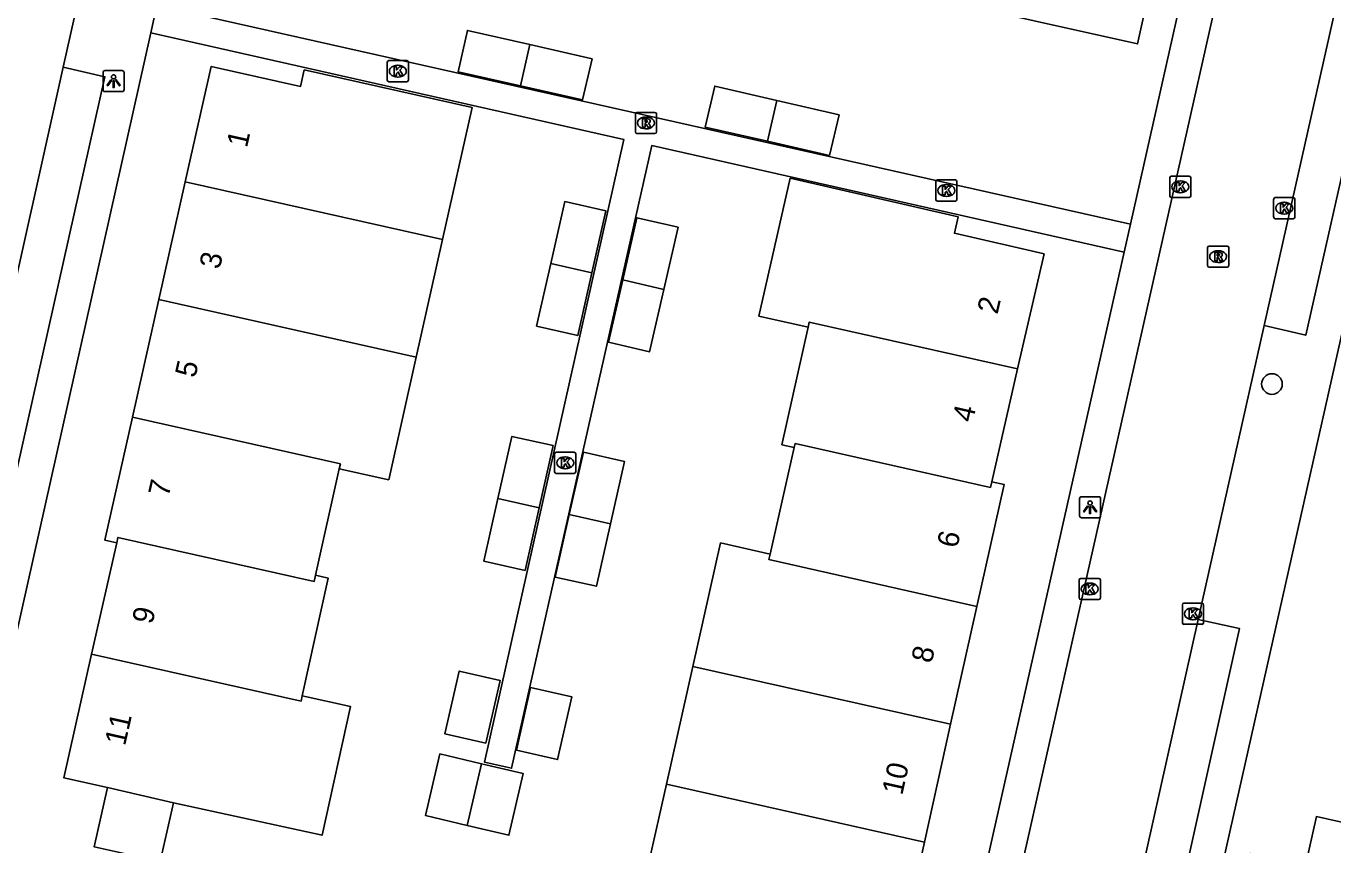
# Model space of a CAD drawing. Extents: x 161771 to 163125, y 382479 to 383177.
# Drawn here: x 162643.4 to 162705.3, y 382625.6 to 382664.4 of the extents above; entities that cross this region are included whole.
import ezdxf

# ---------------------------------------------------------------- set-up
doc = ezdxf.new("R2010")
doc.units = 0
for name, color, linetype in [('IMGEO_Boom', 7, 'Continuous'), ('IMGEO_Kolk', 7, 'Continuous'), ('IMGEO_Lichtpunt', 7, 'Continuous'), ('IMGEO_Pand', 7, 'Continuous'), ('IMGEO_Pand_nummerreeks', 7, 'Continuous'), ('IMGEO_Rijbaan_lokaal_open', 7, 'Continuous'), ('IMGEO_Rioolput', 7, 'Continuous'), ('IMGEO_Voetpad_open', 7, 'Continuous')]:
    doc.layers.add(name, color=color, linetype=linetype)

msp = doc.modelspace()

# ---------------------------------------------------------------- linework, layer by layer
at = {"layer": 'IMGEO_Boom'}
msp.add_circle((162702.369, 382647.447), 0.489, dxfattribs=at)
at = {"layer": 'IMGEO_Kolk'}
for p, q in [((162660.568, 382662.751), (162661.42, 382662.751)), ((162660.493, 382661.825), (162660.493, 382662.677)), ((162660.981, 382662.531), (162661.006, 382662.531)), ((162661.494, 382662.677), (162661.494, 382661.825)), ((162661.42, 382661.751), (162660.568, 382661.751)), ((162661.004, 382661.971), (162660.979, 382661.971)), ((162697.529, 382656.353), (162697.529, 382657.205)), ((162697.604, 382657.279), (162698.456, 382657.279)), ((162698.53, 382657.205), (162698.53, 382656.353)), ((162686.456, 382656.181), (162686.456, 382657.033)), ((162686.531, 382657.107), (162687.383, 382657.107)), ((162686.944, 382656.887), (162686.969, 382656.887)), ((162687.457, 382657.033), (162687.457, 382656.181)), ((162698.017, 382657.059), (162698.042, 382657.059)), ((162687.383, 382656.107), (162686.531, 382656.107)), ((162686.967, 382656.327), (162686.942, 382656.327)), ((162698.456, 382656.279), (162697.604, 382656.279)), ((162698.04, 382656.499), (162698.015, 382656.499)), ((162702.449, 382655.341), (162702.449, 382656.193)), ((162702.524, 382656.267), (162703.376, 382656.267)), ((162702.937, 382656.047), (162702.962, 382656.047)), ((162703.45, 382656.193), (162703.45, 382655.341)), ((162702.96, 382655.487), (162702.935, 382655.487)), ((162703.376, 382655.267), (162702.524, 382655.267)), ((162668.49, 382644.219), (162669.342, 382644.219)), ((162668.415, 382643.293), (162668.415, 382644.145)), ((162668.903, 382643.999), (162668.928, 382643.999)), ((162669.416, 382644.145), (162669.416, 382643.293)), ((162669.342, 382643.219), (162668.49, 382643.219)), ((162668.926, 382643.439), (162668.901, 382643.439)), ((162693.244, 382637.324), (162693.244, 382638.176)), ((162693.319, 382638.25), (162694.171, 382638.25)), ((162693.732, 382638.03), (162693.757, 382638.03)), ((162694.245, 382638.176), (162694.245, 382637.324)), ((162693.755, 382637.47), (162693.73, 382637.47)), ((162694.171, 382637.25), (162693.319, 382637.25)), ((162698.129, 382636.149), (162698.129, 382637.001)), ((162698.204, 382637.075), (162699.056, 382637.075)), ((162698.617, 382636.855), (162698.642, 382636.855)), ((162699.13, 382637.001), (162699.13, 382636.149)), ((162698.64, 382636.295), (162698.615, 382636.295)), ((162699.056, 382636.075), (162698.204, 382636.075))]:
    msp.add_line(p, q, dxfattribs=at)
for points in [[(162660.568, 382662.751), (162661.42, 382662.751)], [(162660.493, 382661.825), (162660.493, 382662.677)], [(162660.814, 382662.451), (162660.937, 382662.451), (162660.937, 382662.3), (162661.067, 382662.451), (162661.231, 382662.451), (162661.085, 382662.3), (162661.238, 382662.051), (162661.086, 382662.051), (162661.001, 382662.215), (162660.937, 382662.148), (162660.937, 382662.051), (162660.814, 382662.051), (162660.814, 382662.451)], [(162661.494, 382662.677), (162661.494, 382661.825)], [(162661.42, 382661.751), (162660.568, 382661.751)], [(162697.529, 382656.353), (162697.529, 382657.205)], [(162697.604, 382657.279), (162698.456, 382657.279)], [(162698.53, 382657.205), (162698.53, 382656.353)], [(162686.456, 382656.181), (162686.456, 382657.033)], [(162686.531, 382657.107), (162687.383, 382657.107)], [(162686.777, 382656.807), (162686.9, 382656.807), (162686.9, 382656.656), (162687.03, 382656.807), (162687.194, 382656.807), (162687.048, 382656.656), (162687.201, 382656.407), (162687.049, 382656.407), (162686.964, 382656.571), (162686.9, 382656.504), (162686.9, 382656.407), (162686.777, 382656.407), (162686.777, 382656.807)], [(162687.457, 382657.033), (162687.457, 382656.181)], [(162697.85, 382656.979), (162697.973, 382656.979), (162697.973, 382656.828), (162698.103, 382656.979), (162698.267, 382656.979), (162698.121, 382656.828), (162698.274, 382656.579), (162698.122, 382656.579), (162698.037, 382656.743), (162697.973, 382656.676), (162697.973, 382656.579), (162697.85, 382656.579), (162697.85, 382656.979)], [(162687.383, 382656.107), (162686.531, 382656.107)], [(162698.456, 382656.279), (162697.604, 382656.279)], [(162702.449, 382655.341), (162702.449, 382656.193)], [(162702.524, 382656.267), (162703.376, 382656.267)], [(162702.77, 382655.967), (162702.893, 382655.967), (162702.893, 382655.816), (162703.023, 382655.967), (162703.187, 382655.967), (162703.041, 382655.816), (162703.194, 382655.567), (162703.042, 382655.567), (162702.957, 382655.731), (162702.893, 382655.664), (162702.893, 382655.567), (162702.77, 382655.567), (162702.77, 382655.967)], [(162703.45, 382656.193), (162703.45, 382655.341)], [(162703.376, 382655.267), (162702.524, 382655.267)], [(162668.49, 382644.219), (162669.342, 382644.219)], [(162668.415, 382643.293), (162668.415, 382644.145)], [(162668.736, 382643.919), (162668.859, 382643.919), (162668.859, 382643.768), (162668.989, 382643.919), (162669.153, 382643.919), (162669.007, 382643.768), (162669.16, 382643.519), (162669.008, 382643.519), (162668.923, 382643.683), (162668.859, 382643.616), (162668.859, 382643.519), (162668.736, 382643.519), (162668.736, 382643.919)], [(162669.416, 382644.145), (162669.416, 382643.293)], [(162669.342, 382643.219), (162668.49, 382643.219)], [(162693.244, 382637.324), (162693.244, 382638.176)], [(162693.319, 382638.25), (162694.171, 382638.25)], [(162694.245, 382638.176), (162694.245, 382637.324)], [(162693.565, 382637.95), (162693.688, 382637.95), (162693.688, 382637.799), (162693.818, 382637.95), (162693.982, 382637.95), (162693.836, 382637.799), (162693.989, 382637.55), (162693.837, 382637.55), (162693.752, 382637.714), (162693.688, 382637.647), (162693.688, 382637.55), (162693.565, 382637.55), (162693.565, 382637.95)], [(162694.171, 382637.25), (162693.319, 382637.25)], [(162698.129, 382636.149), (162698.129, 382637.001)], [(162698.204, 382637.075), (162699.056, 382637.075)], [(162698.45, 382636.775), (162698.573, 382636.775), (162698.573, 382636.624), (162698.703, 382636.775), (162698.867, 382636.775), (162698.721, 382636.624), (162698.874, 382636.375), (162698.722, 382636.375), (162698.637, 382636.539), (162698.573, 382636.472), (162698.573, 382636.375), (162698.45, 382636.375), (162698.45, 382636.775)], [(162699.13, 382637.001), (162699.13, 382636.149)], [(162699.056, 382636.075), (162698.204, 382636.075)]]:
    msp.add_lwpolyline(points, dxfattribs=at)
for centre, start, end in [((162660.57, 382662.675), 91.55205, 178.44795), ((162660.57, 382662.675), 91.55205, 178.44795), ((162661.418, 382662.675), 1.55205, 88.44795), ((162661.418, 382662.675), 1.55205, 88.44795), ((162660.57, 382661.827), 181.55205, 268.44795), ((162660.57, 382661.827), 181.55205, 268.44795), ((162661.418, 382661.827), 271.55205, 358.44795), ((162661.418, 382661.827), 271.55205, 358.44795), ((162697.606, 382657.203), 91.55205, 178.44795), ((162697.606, 382657.203), 91.55205, 178.44795), ((162698.454, 382657.203), 1.55205, 88.44795), ((162698.454, 382657.203), 1.55205, 88.44795), ((162686.533, 382657.031), 91.55205, 178.44795), ((162686.533, 382657.031), 91.55205, 178.44795), ((162687.381, 382657.031), 1.55205, 88.44795), ((162687.381, 382657.031), 1.55205, 88.44795), ((162686.533, 382656.183), 181.55205, 268.44795), ((162686.533, 382656.183), 181.55205, 268.44795), ((162687.381, 382656.183), 271.55205, 358.44795), ((162687.381, 382656.183), 271.55205, 358.44795), ((162697.606, 382656.355), 181.55205, 268.44795), ((162697.606, 382656.355), 181.55205, 268.44795), ((162698.454, 382656.355), 271.55205, 358.44795), ((162698.454, 382656.355), 271.55205, 358.44795), ((162702.526, 382656.191), 91.55205, 178.44795), ((162702.526, 382656.191), 91.55205, 178.44795), ((162703.374, 382656.191), 1.55205, 88.44795), ((162703.374, 382656.191), 1.55205, 88.44795), ((162702.526, 382655.343), 181.55205, 268.44795), ((162702.526, 382655.343), 181.55205, 268.44795), ((162703.374, 382655.343), 271.55205, 358.44795), ((162703.374, 382655.343), 271.55205, 358.44795), ((162668.492, 382644.143), 91.55205, 178.44795), ((162668.492, 382644.143), 91.55205, 178.44795), ((162669.34, 382644.143), 1.55205, 88.44795), ((162669.34, 382644.143), 1.55205, 88.44795), ((162668.492, 382643.295), 181.55205, 268.44795), ((162668.492, 382643.295), 181.55205, 268.44795), ((162669.34, 382643.295), 271.55205, 358.44795), ((162669.34, 382643.295), 271.55205, 358.44795), ((162693.321, 382638.174), 91.55205, 178.44795), ((162693.321, 382638.174), 91.55205, 178.44795), ((162694.169, 382638.174), 1.55205, 88.44795), ((162694.169, 382638.174), 1.55205, 88.44795), ((162693.321, 382637.326), 181.55205, 268.44795), ((162693.321, 382637.326), 181.55205, 268.44795), ((162694.169, 382637.326), 271.55205, 358.44795), ((162694.169, 382637.326), 271.55205, 358.44795), ((162698.206, 382636.999), 91.55205, 178.44795), ((162698.206, 382636.999), 91.55205, 178.44795), ((162699.054, 382636.999), 1.55205, 88.44795), ((162699.054, 382636.999), 1.55205, 88.44795), ((162698.206, 382636.151), 181.55205, 268.44795), ((162698.206, 382636.151), 181.55205, 268.44795), ((162699.054, 382636.151), 271.55205, 358.44795), ((162699.054, 382636.151), 271.55205, 358.44795)]:
    msp.add_arc(centre, 0.0765, start, end, dxfattribs=at)
for centre, major_axis, ratio, start_param, end_param in [((162660.98, 382662.251), (-0.387, 0.002), 0.722429, 4.712389, 7.853982), ((162661.005, 382662.251), (-0.39, 0.002), 0.717154, 1.570796, 4.712389), ((162686.943, 382656.607), (-0.387, 0.002), 0.722429, 4.712389, 7.853982), ((162686.968, 382656.607), (-0.39, 0.002), 0.717154, 1.570796, 4.712389), ((162698.016, 382656.779), (-0.387, 0.002), 0.722429, 4.712389, 7.853982), ((162698.041, 382656.779), (-0.39, 0.002), 0.717154, 1.570796, 4.712389), ((162702.936, 382655.767), (-0.387, 0.002), 0.722429, 4.712389, 7.853982), ((162702.961, 382655.767), (-0.39, 0.002), 0.717154, 1.570796, 4.712389), ((162668.902, 382643.719), (-0.387, 0.002), 0.722429, 4.712389, 7.853982), ((162668.927, 382643.719), (-0.39, 0.002), 0.717154, 1.570796, 4.712389), ((162693.731, 382637.75), (-0.387, 0.002), 0.722429, 4.712389, 7.853982), ((162693.756, 382637.75), (-0.39, 0.002), 0.717154, 1.570796, 4.712389), ((162698.616, 382636.575), (-0.387, 0.002), 0.722429, 4.712389, 7.853982), ((162698.641, 382636.575), (-0.39, 0.002), 0.717154, 1.570796, 4.712389)]:
    msp.add_ellipse(centre, major_axis=major_axis, ratio=ratio, start_param=start_param, end_param=end_param, dxfattribs=at)
at = {"layer": 'IMGEO_Lichtpunt'}
for p, q in [((162647.04, 382662.184), (162647.04, 382661.377)), ((162647.04, 382662.184), (162647.04, 382661.377)), ((162647.942, 382662.279), (162647.134, 382662.279)), ((162647.942, 382662.279), (162647.134, 382662.279)), ((162648.036, 382661.377), (162648.036, 382662.184)), ((162648.036, 382661.377), (162648.036, 382662.184)), ((162647.134, 382661.283), (162647.942, 382661.283)), ((162647.134, 382661.283), (162647.942, 382661.283)), ((162693.261, 382642.02), (162693.261, 382641.213)), ((162693.261, 382642.02), (162693.261, 382641.213)), ((162694.163, 382642.115), (162693.355, 382642.115)), ((162694.163, 382642.115), (162693.355, 382642.115)), ((162694.257, 382641.213), (162694.257, 382642.02)), ((162694.257, 382641.213), (162694.257, 382642.02)), ((162693.355, 382641.119), (162694.163, 382641.119)), ((162693.355, 382641.119), (162694.163, 382641.119))]:
    msp.add_line(p, q, dxfattribs=at)
for points in [[(162647.414, 382661.848), (162647.453, 382661.82), (162647.265, 382661.558), (162647.227, 382661.585), (162647.414, 382661.848)], [(162647.516, 382661.8), (162647.563, 382661.8), (162647.563, 382661.478), (162647.516, 382661.478), (162647.516, 382661.8)], [(162647.626, 382661.82), (162647.664, 382661.847), (162647.851, 382661.585), (162647.812, 382661.557), (162647.626, 382661.82)], [(162693.635, 382641.684), (162693.674, 382641.656), (162693.486, 382641.394), (162693.448, 382641.421), (162693.635, 382641.684)], [(162693.737, 382641.636), (162693.784, 382641.636), (162693.784, 382641.314), (162693.737, 382641.314), (162693.737, 382641.636)], [(162693.847, 382641.656), (162693.885, 382641.683), (162694.072, 382641.421), (162694.033, 382641.393), (162693.847, 382641.656)]]:
    msp.add_lwpolyline(points, dxfattribs=at)
for centre in [(162647.539, 382661.982), (162693.76, 382641.818)]:
    msp.add_circle(centre, 0.0994, dxfattribs=at)
for centre, start, end in [((162647.134, 382662.184), 90, 180), ((162647.134, 382662.184), 90, 180), ((162647.942, 382662.184), 0, 90), ((162647.942, 382662.184), 0, 90), ((162647.134, 382661.377), 180, 270), ((162647.134, 382661.377), 180, 270), ((162647.942, 382661.377), 270, 0), ((162647.942, 382661.377), 270, 360), ((162693.355, 382642.02), 90, 180), ((162693.355, 382642.02), 90, 180), ((162694.163, 382642.02), 0, 90), ((162694.163, 382642.02), 0, 90), ((162693.355, 382641.213), 180, 270), ((162693.355, 382641.213), 180, 270), ((162694.163, 382641.213), 270, 0), ((162694.163, 382641.213), 270, 360)]:
    msp.add_arc(centre, 0.0946, start, end, dxfattribs=at)
at = {"layer": 'IMGEO_Pand'}
for points in [[(162697.292, 382669.389), (162696.008, 382663.544), (162686.228, 382665.743)], [(162666.794, 382661.558), (162663.845, 382662.225), (162664.29, 382664.178), (162667.238, 382663.507)], [(162667.238, 382663.507), (162670.185, 382662.835), (162669.735, 382660.893), (162666.794, 382661.558)], [(162666.794, 382661.558), (162667.238, 382663.507)], [(162663.114, 382654.281), (162664.517, 382660.531), (162656.564, 382662.313), (162656.388, 382661.53), (162652.16, 382662.479), (162650.933, 382657.014)], [(162678.487, 382658.932), (162675.543, 382659.602), (162675.99, 382661.547), (162678.936, 382660.864)], [(162678.936, 382660.864), (162681.881, 382660.18), (162681.422, 382658.265), (162678.487, 382658.932)], [(162678.936, 382660.864), (162678.487, 382658.932)], [(162690.33, 382648.165), (162691.579, 382653.607), (162687.335, 382654.58), (162687.514, 382655.364), (162679.57, 382657.185), (162678.075, 382650.663), (162680.421, 382650.136)], [(162650.933, 382657.014), (162649.683, 382651.445)], [(162663.114, 382654.281), (162650.933, 382657.014)], [(162670.179, 382652.704), (162670.842, 382655.635), (162668.897, 382656.081), (162668.231, 382653.149)], [(162673.582, 382651.925), (162674.256, 382654.865), (162672.311, 382655.315), (162671.637, 382652.37)], [(162661.865, 382648.711), (162663.114, 382654.281)], [(162668.231, 382653.149), (162667.559, 382650.188), (162669.508, 382649.739), (162670.179, 382652.704)], [(162668.231, 382653.149), (162670.179, 382652.704)], [(162671.637, 382652.37), (162670.964, 382649.425), (162672.906, 382648.974), (162673.582, 382651.925)], [(162673.582, 382651.925), (162671.637, 382652.37)], [(162649.683, 382651.445), (162648.432, 382645.874)], [(162661.865, 382648.711), (162649.683, 382651.445)], [(162680.421, 382650.136), (162680.47, 382650.375), (162690.33, 382648.165)], [(162680.421, 382650.136), (162679.17, 382644.573), (162679.752, 382644.443)], [(162658.217, 382643.438), (162660.565, 382642.919), (162661.865, 382648.711)], [(162689.105, 382642.826), (162690.33, 382648.165)], [(162648.432, 382645.874), (162647.125, 382640.051), (162647.685, 382639.93)], [(162648.432, 382645.874), (162658.273, 382643.667), (162658.217, 382643.438)], [(162665.732, 382642.03), (162666.39, 382644.967), (162668.341, 382644.533), (162667.68, 382641.589)], [(162669.11, 382641.266), (162669.778, 382644.217), (162671.729, 382643.779), (162671.059, 382640.824)], [(162679.752, 382644.443), (162678.618, 382639.402)], [(162689.105, 382642.826), (162689.043, 382642.555), (162679.793, 382644.631), (162679.752, 382644.443)], [(162657.102, 382638.397), (162658.217, 382643.438)], [(162688.403, 382636.923), (162689.688, 382642.693), (162689.105, 382642.826)], [(162667.68, 382641.589), (162667.014, 382638.626), (162665.066, 382639.062), (162665.732, 382642.03)], [(162665.732, 382642.03), (162667.68, 382641.589)], [(162671.059, 382640.824), (162670.391, 382637.878), (162668.442, 382638.314), (162669.11, 382641.266)], [(162671.059, 382640.824), (162669.11, 382641.266)], [(162647.685, 382639.93), (162646.501, 382634.66)], [(162647.685, 382639.93), (162647.744, 382640.187), (162657.035, 382638.104), (162657.102, 382638.397)], [(162678.618, 382639.402), (162676.272, 382639.929), (162674.958, 382634.084)], [(162688.403, 382636.923), (162678.559, 382639.138), (162678.618, 382639.402)], [(162656.46, 382632.695), (162657.692, 382638.267), (162657.102, 382638.397)], [(162687.16, 382631.345), (162688.403, 382636.923)], [(162646.501, 382634.66), (162645.187, 382628.81), (162647.246, 382628.349)], [(162656.46, 382632.695), (162656.41, 382632.443), (162646.501, 382634.66)], [(162665.155, 382630.454), (162663.221, 382630.892), (162663.901, 382633.859), (162665.843, 382633.413), (162665.155, 382630.454)], [(162674.958, 382634.084), (162673.704, 382628.507)], [(162687.16, 382631.345), (162674.958, 382634.084)], [(162667.279, 382633.083), (162669.222, 382632.645), (162668.558, 382629.675), (162666.613, 382630.114), (162667.279, 382633.083)], [(162650.371, 382627.635), (162657.408, 382626.09), (162658.746, 382632.189), (162656.46, 382632.695)], [(162685.917, 382625.767), (162687.16, 382631.345)], [(162664.953, 382629.48), (162662.984, 382629.941), (162662.304, 382627.023), (162664.269, 382626.56)], [(162664.953, 382629.48), (162664.269, 382626.56)], [(162664.269, 382626.56), (162666.25, 382626.093), (162666.922, 382629.019), (162664.953, 382629.48)], [(162650.371, 382627.635), (162649.747, 382624.85), (162646.619, 382625.551), (162647.246, 382628.349)], [(162647.246, 382628.349), (162650.371, 382627.635)], [(162673.704, 382628.507), (162672.4, 382622.706), (162678.278, 382621.384)], [(162685.917, 382625.767), (162673.704, 382628.507)], [(162710.432, 382625.633), (162707.605, 382613.165), (162700.638, 382614.728), (162701.626, 382619.12), (162700.067, 382619.47), (162701.344, 382625.235), (162703.961, 382624.656), (162704.476, 382626.979), (162710.432, 382625.633)], [(162681.435, 382620.69), (162684.627, 382619.975), (162685.917, 382625.767)]]:
    msp.add_lwpolyline(points, dxfattribs=at)
at = {"layer": 'IMGEO_Rijbaan_lokaal_open'}
for points in [[(162689.019, 382617.923), (162702.214, 382676.655)], [(162702.006, 382650.214), (162707.299, 382673.793)], [(162645.155, 382662.439), (162646.399, 382668.009), (162646.471, 382668.329)], [(162645.155, 382662.439), (162642.064, 382648.604), (162638.592, 382633.065)], [(162698.882, 382636.297), (162702.006, 382650.214)], [(162694.939, 382618.734), (162698.882, 382636.297)]]:
    msp.add_lwpolyline(points, dxfattribs=at)
at = {"layer": 'IMGEO_Rioolput'}
for p, q in [((162672.312, 382660.301), (162673.164, 382660.301)), ((162672.237, 382659.375), (162672.237, 382660.227)), ((162672.725, 382660.081), (162672.75, 382660.081)), ((162673.238, 382660.227), (162673.238, 382659.375)), ((162673.164, 382659.301), (162672.312, 382659.301)), ((162672.748, 382659.521), (162672.723, 382659.521)), ((162699.32, 382653.05), (162699.32, 382653.902)), ((162699.395, 382653.976), (162700.247, 382653.976)), ((162699.808, 382653.756), (162699.833, 382653.756)), ((162700.321, 382653.902), (162700.321, 382653.05)), ((162700.247, 382652.976), (162699.395, 382652.976)), ((162699.831, 382653.196), (162699.806, 382653.196))]:
    msp.add_line(p, q, dxfattribs=at)
for points in [[(162672.312, 382660.301), (162673.164, 382660.301)], [(162672.237, 382659.375), (162672.237, 382660.227)], [(162672.826, 382659.999), (162672.574, 382660.001), (162672.574, 382659.601)], [(162672.574, 382659.601), (162672.698, 382659.601), (162672.698, 382659.763), (162672.709, 382659.763)], [(162672.752, 382659.92), (162672.698, 382659.92), (162672.698, 382659.839)], [(162672.698, 382659.839), (162672.75, 382659.839)], [(162672.756, 382659.734), (162672.827, 382659.601), (162672.967, 382659.601), (162672.902, 382659.727)], [(162673.238, 382660.227), (162673.238, 382659.375)], [(162673.164, 382659.301), (162672.312, 382659.301)], [(162699.32, 382653.05), (162699.32, 382653.902)], [(162699.395, 382653.976), (162700.247, 382653.976)], [(162699.909, 382653.674), (162699.657, 382653.676), (162699.657, 382653.276)], [(162699.835, 382653.595), (162699.781, 382653.595), (162699.781, 382653.514)], [(162699.781, 382653.514), (162699.833, 382653.514)], [(162700.321, 382653.902), (162700.321, 382653.05)], [(162700.247, 382652.976), (162699.395, 382652.976)], [(162699.657, 382653.276), (162699.781, 382653.276), (162699.781, 382653.438), (162699.792, 382653.438)], [(162699.839, 382653.409), (162699.91, 382653.276), (162700.05, 382653.276), (162699.985, 382653.402)]]:
    msp.add_lwpolyline(points, dxfattribs=at)
for centre, radius, start, end in [((162672.314, 382660.225), 0.0765, 91.55205, 178.44795), ((162672.314, 382660.225), 0.0765, 91.55205, 178.44795), ((162673.162, 382660.225), 0.0765, 1.55205, 88.44795), ((162673.162, 382660.225), 0.0765, 1.55205, 88.44795), ((162672.708, 382659.71), 0.0533, 26.02933, 88.69889), ((162672.734, 382660.028), 0.19, 274.7715, 282.96867), ((162672.758, 382659.824), 0.0964, 77.00612, 93.18647), ((162672.772, 382659.881), 0.0378, 276.66336, 79.67722), ((162672.825, 382659.889), 0.109, 350.36119, 89.41601), ((162672.823, 382659.889), 0.112, 277.58423, 350.98172), ((162672.807, 382659.674), 0.108, 29.51342, 73.79051), ((162672.314, 382659.377), 0.0765, 181.55205, 268.44795), ((162672.314, 382659.377), 0.0765, 181.55205, 268.44795), ((162673.162, 382659.377), 0.0765, 271.55205, 358.44795), ((162673.162, 382659.377), 0.0765, 271.55205, 358.44795), ((162699.397, 382653.9), 0.0765, 91.55205, 178.44795), ((162699.397, 382653.9), 0.0765, 91.55205, 178.44795), ((162699.817, 382653.703), 0.19, 274.7715, 282.96867), ((162699.841, 382653.499), 0.0964, 77.00612, 93.18647), ((162699.855, 382653.556), 0.0378, 276.66336, 79.67722), ((162699.908, 382653.564), 0.109, 350.36119, 89.41601), ((162699.906, 382653.564), 0.112, 277.58423, 350.98172), ((162700.245, 382653.9), 0.0765, 1.55205, 88.44795), ((162700.245, 382653.9), 0.0765, 1.55205, 88.44795), ((162699.397, 382653.052), 0.0765, 181.55205, 268.44795), ((162699.397, 382653.052), 0.0765, 181.55205, 268.44795), ((162699.791, 382653.385), 0.0533, 26.02933, 88.69889), ((162699.89, 382653.349), 0.108, 29.51342, 73.79051), ((162700.245, 382653.052), 0.0765, 271.55205, 358.44795), ((162700.245, 382653.052), 0.0765, 271.55205, 358.44795)]:
    msp.add_arc(centre, radius, start, end, dxfattribs=at)
for centre, major_axis, ratio, start_param, end_param in [((162672.724, 382659.801), (-0.387, 0.002), 0.722429, 4.712389, 7.853982), ((162672.749, 382659.801), (-0.39, 0.002), 0.717154, 1.570796, 4.712389), ((162699.807, 382653.476), (-0.387, 0.002), 0.722429, 4.712389, 7.853982), ((162699.832, 382653.476), (-0.39, 0.002), 0.717154, 1.570796, 4.712389)]:
    msp.add_ellipse(centre, major_axis=major_axis, ratio=ratio, start_param=start_param, end_param=end_param, dxfattribs=at)
at = {"layer": 'IMGEO_Voetpad_open'}
for points in [[(162698.037, 382615.869), (162712.056, 382678.166)], [(162700.608, 382677.107), (162699.68, 382672.847), (162695.667, 382655.016)], [(162707.299, 382673.793), (162709.286, 382673.345), (162703.97, 382649.758), (162702.006, 382650.214)], [(162649.585, 382665.364), (162649.296, 382664.072)], [(162649.585, 382665.364), (162695.667, 382655.016)], [(162649.296, 382664.072), (162636.509, 382606.935), (162636.331, 382606.03)], [(162695.368, 382653.689), (162673.009, 382658.73), (162666.379, 382629.265), (162665.103, 382629.55), (162671.693, 382659.013), (162649.296, 382664.072)], [(162638.592, 382633.065), (162640.531, 382632.6), (162647.131, 382661.99), (162645.155, 382662.439)], [(162695.667, 382655.016), (162695.368, 382653.689)], [(162695.368, 382653.689), (162687.403, 382618.3)], [(162698.882, 382636.297), (162700.827, 382635.884), (162696.914, 382618.279), (162694.939, 382618.734)]]:
    msp.add_lwpolyline(points, dxfattribs=at)

# ---------------------------------------------------------------- texts
at = {"layer": 'IMGEO_Pand_nummerreeks'}
for s, rotation, p in [('1', 77.3493, (162653.85, 382658.592)), ('3', 77.3493, (162652.558, 382652.84)), ('2', 77.07428, (162689.376, 382650.712)), ('5', 77.3493, (162651.406, 382647.705)), ('4', 77.07428, (162688.201, 382645.593)), ('7', 77.3493, (162650.14, 382642.065)), ('6', 77.44098, (162687.472, 382639.643)), ('9', 77.33784, (162649.375, 382636.044)), ('8', 77.44098, (162686.259, 382634.197)), ('11', 77.33784, (162648.082, 382630.292)), ('10', 77.44098, (162684.868, 382627.953))]:
    msp.add_text(s, height=1, rotation=rotation, dxfattribs=at).set_placement(p)

doc.saveas('drawing.dxf')
